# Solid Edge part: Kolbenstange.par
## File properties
Username: ahadarics
Dokumentum tartalom típus: 0
Author: ahadarics
Last saved by: ahadarics
Revision: 80
Sűrűség: 0,000 kg/m^3
Pontosság: 0,990
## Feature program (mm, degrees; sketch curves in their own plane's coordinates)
base feature "unnamed BaseFeature 1"
sketch for "unnamed Protrusion 1" plane through (64, 0, 0) normal (1, 0, 0) x-axis (0, 1, 0)
  circle centre (0, 0) radius 12.5
extrude "unnamed Protrusion 1" add finite 33 along -normal
thread "Menet_2"  ThreadDepth = 22 mm
chamfer "Letörés_1" setback 0.7
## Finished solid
Body 1: solid body, 13 faces, 23 edges, 12 vertices.
  Faces by surface: plane 9, cylinder 3, cone 1
  Edges by curve: line 12, circle 11
Bounding box of the edges (mm): 150.500 x 25.000 x 25.000, from (-86.5, -12.5, -12.5) to (64, 12.5, 12.5).
Cylindrical faces by radius (mm): R5 x2, R12.5 x1
Conical faces (half-angle, radius in mm at the cone's reference point): 45 deg R4.3 x1
Planar faces by outward normal: +x 3, +z 1, -x 4, -z 1
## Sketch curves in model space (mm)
circle centre (64, 0, 0) radius 12.5
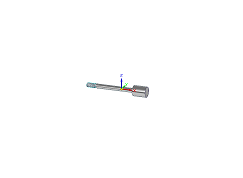
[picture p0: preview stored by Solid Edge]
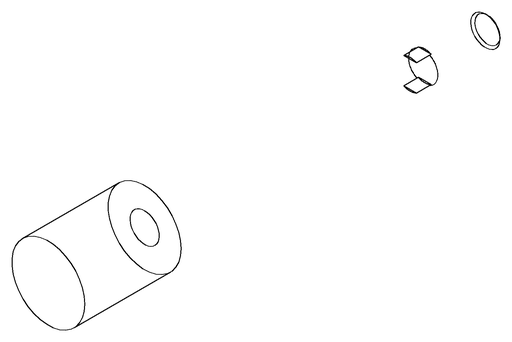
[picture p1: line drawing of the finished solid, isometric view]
